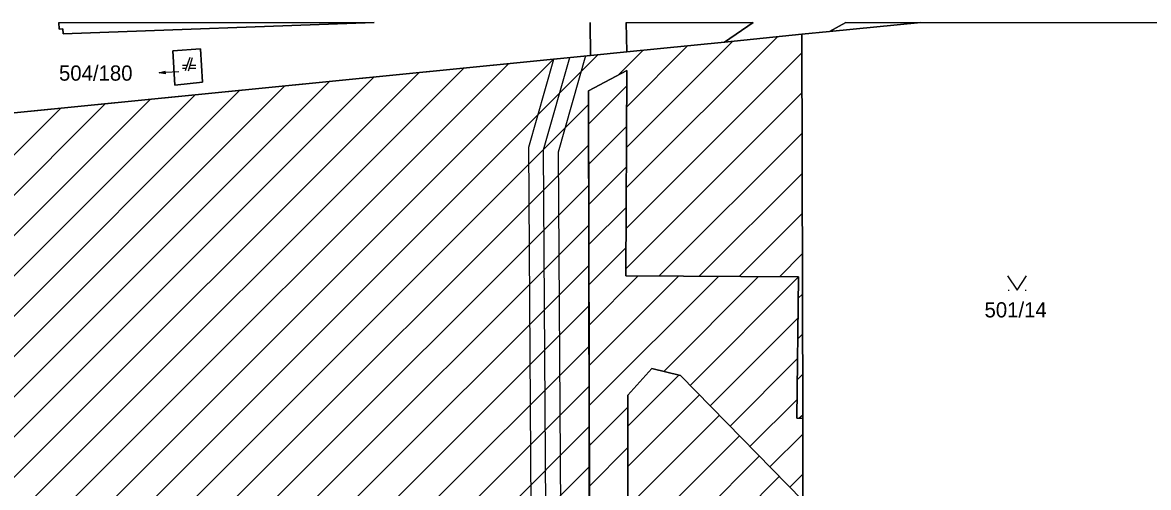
# Model space of a CAD drawing. Extents: x -264309 to -263505, y -1242443 to -1241763.
# Drawn here: x -264073.7 to -263955.2, y -1242005.9 to -1241957 of the extents above; entities that cross this region are included whole.
import ezdxf

# ---------------------------------------------------------------- set-up
doc = ezdxf.new("R2010")
doc.units = 0
for name, color, linetype in [('KN_2019_08_16', 7, 'Continuous'), ('KN_2019_08_16_KLADPAR', 7, 'Continuous'), ('SRAFY_PARCELY', 7, 'Continuous')]:
    doc.layers.add(name, color=color, linetype=linetype)

msp = doc.modelspace()

# ---------------------------------------------------------------- linework, layer by layer
at = {"layer": 'KN_2019_08_16'}
msp.add_lwpolyline([(-264014.44, -1241960.47), (-264017.32, -1241970.61), (-264016.97, -1242024.38), (-264017.48, -1242038.84), (-264017.6, -1242045.19), (-264017.74, -1242052.08), (-264018.07, -1242069.28), (-264018.14, -1242072.77), (-264019.68, -1242072.72), (-264021.23, -1242072.66), (-264021.16, -1242069.28), (-264020.83, -1242052.09), (-264020.73, -1242046.57), (-264020.58, -1242038.83), (-264020.07, -1242024.34), (-264020.4, -1241970.09), (-264017.76, -1241960.8), (-264016.1, -1241960.64)], close=True, dxfattribs=at)
msp.add_lwpolyline([(-264019.68, -1242072.72), (-264019.61, -1242069.28), (-264019.28, -1242052.09), (-264019.16, -1242045.88), (-264019.03, -1242038.83), (-264018.52, -1242024.36), (-264018.86, -1241970.35), (-264016.1, -1241960.64)], dxfattribs=at)
at = {"layer": 'KN_2019_08_16_KLADPAR'}
for p, q in [((-264069.82, -1241957.65), (-264069.84, -1241956.96)), ((-264069.84, -1241956.96), (-264036.67, -1241956.96)), ((-264036.67, -1241956.96), (-264069.4, -1241958.16)), ((-264010.18, -1241956.96), (-263996.79, -1241956.96)), ((-264010.08, -1241960.03), (-264010.18, -1241956.96)), ((-263996.79, -1241956.96), (-263999.84, -1241959.01)), ((-263988.77, -1241957.91), (-263979.18, -1241956.96)), ((-263979.18, -1241956.96), (-263988.77, -1241957.91)), ((-263988.77, -1241957.91), (-263987.05, -1241956.96)), ((-263987.05, -1241956.96), (-263979.18, -1241956.96)), ((-263979.18, -1241956.96), (-263944.96, -1241956.96)), ((-264069.41, -1241957.63), (-264069.82, -1241957.65)), ((-264069.4, -1241958.16), (-264069.41, -1241957.63)), ((-263999.84, -1241959.01), (-263991.69, -1241958.2)), ((-263991.69, -1241958.2), (-263988.77, -1241957.91)), ((-263991.69, -1241958.2), (-263991.6, -1241998.65)), ((-263991.6, -1241998.65), (-263991.69, -1241958.2)), ((-264010.08, -1241960.03), (-263999.84, -1241959.01)), ((-263999.84, -1241959.01), (-264010.08, -1241960.03)), ((-264080.59, -1241967.06), (-264013.93, -1241960.42)), ((-264056.08, -1241960.64), (-264056.57, -1241962.04)), ((-264056.22, -1241962.04), (-264055.8, -1241960.64)), ((-264013.93, -1241960.42), (-264010.08, -1241960.03)), ((-264056.37, -1241961.48), (-264056.85, -1241961.48)), ((-264056.85, -1241961.76), (-264056.47, -1241961.76)), ((-264056.14, -1241961.76), (-264055.45, -1241961.76)), ((-264055.45, -1241961.48), (-264056.05, -1241961.48)), ((-264010.09, -1241962), (-264014.12, -1241964.15)), ((-264010.2, -1241983.62), (-264010.09, -1241962)), ((-264058.6, -1241962.35), (-264059.31, -1241962.24)), ((-264014.12, -1241964.15), (-264013.98, -1242038.21)), ((-263992.03, -1241983.73), (-264010.2, -1241983.62)), ((-263992.22, -1241998.61), (-263992.03, -1241983.73)), ((-263969.99, -1241985.12), (-263969.89, -1241985.12)), ((-263968.19, -1241985.12), (-263968.09, -1241985.12)), ((-263991.6, -1241998.65), (-263992.22, -1241998.61)), ((-263991.58, -1242007.28), (-263991.6, -1241998.65))]:
    msp.add_line(p, q, dxfattribs=at)
for points in [[(-264013.95, -1241956.96), (-264013.93, -1241960.42), (-264080.59, -1241967.06)], [(-264069.84, -1241956.96), (-264069.82, -1241957.65), (-264069.41, -1241957.63), (-264069.4, -1241958.16), (-264036.67, -1241956.96)], [(-264010.18, -1241956.96), (-264010.08, -1241960.03), (-264013.93, -1241960.42), (-264013.95, -1241956.96)], [(-263987.05, -1241956.96), (-263988.77, -1241957.91), (-263991.69, -1241958.2), (-263999.84, -1241959.01), (-263996.79, -1241956.96)], [(-264057.21, -1241962.14), (-264059.31, -1241962.24), (-264058.61, -1241962.07)], [(-264013.98, -1242038.21), (-264014.12, -1241964.15), (-264010.09, -1241962), (-264010.2, -1241983.62), (-263992.03, -1241983.73), (-263992.22, -1241998.61), (-263991.6, -1241998.65), (-263991.58, -1242007.28), (-264004.45, -1241994.11), (-264007.47, -1241993.39), (-264009.98, -1241996.19), (-264009.97, -1242022.53)], [(-263970.04, -1241983.62), (-263969.04, -1241985.12), (-263968.04, -1241983.62)]]:
    msp.add_lwpolyline(points, dxfattribs=at)
for points in [[(-264057.65, -1241963.54), (-264054.72, -1241963.25), (-264054.95, -1241959.73), (-264057.87, -1241959.95)], [(-264057.87, -1241959.95), (-264054.95, -1241959.73), (-264054.72, -1241963.25), (-264057.65, -1241963.54)], [(-263991.54, -1242026.1), (-264000.91, -1242025.57), (-264009.05, -1242025.11), (-264009.97, -1242022.53), (-264009.98, -1241996.19), (-264007.47, -1241993.39), (-264004.45, -1241994.11), (-263991.58, -1242007.28)]]:
    msp.add_lwpolyline(points, close=True, dxfattribs=at)
at = {"layer": 'SRAFY_PARCELY'}
for p, q in [((-264010.15, -1241974.36), (-263994.24, -1241958.45)), ((-264010.13, -1241970.1), (-263998.95, -1241958.92)), ((-264010.11, -1241965.83), (-264003.67, -1241959.39)), ((-264102.68, -1242045.68), (-264017.81, -1241960.81)), ((-264101.29, -1242048.53), (-264013.1, -1241960.34)), ((-264011.01, -1241962.49), (-264008.38, -1241959.86)), ((-264010.17, -1241978.63), (-263991.69, -1241960.14)), ((-264105.47, -1242039.98), (-264027.23, -1241961.75)), ((-264104.08, -1242042.83), (-264022.52, -1241961.28)), ((-264109.63, -1242031.42), (-264041.37, -1241963.15)), ((-264108.26, -1242034.28), (-264036.66, -1241962.68)), ((-264106.86, -1242037.13), (-264031.95, -1241962.21)), ((-264113.66, -1242022.72), (-264055.51, -1241964.56)), ((-264112.32, -1242025.62), (-264050.79, -1241964.09)), ((-264110.98, -1242028.52), (-264046.08, -1241963.62)), ((-264014.11, -1241967.64), (-264010.1, -1241963.62)), ((-264010.2, -1241982.89), (-263991.68, -1241964.37)), ((-264116.35, -1242016.92), (-264064.93, -1241965.5)), ((-264115, -1242019.82), (-264060.22, -1241965.03)), ((-264099.9, -1242051.38), (-264014.12, -1241965.6)), ((-264117.69, -1242014.02), (-264069.64, -1241965.97)), ((-264014.11, -1241971.87), (-264010.12, -1241967.89)), ((-264006.7, -1241983.64), (-263991.67, -1241968.61)), ((-264098.59, -1242054.31), (-264014.11, -1241969.83)), ((-264014.1, -1241976.11), (-264010.14, -1241972.15)), ((-264002.49, -1241983.67), (-263991.66, -1241972.84)), ((-264097.28, -1242057.24), (-264014.1, -1241974.07)), ((-264014.09, -1241980.34), (-264010.16, -1241976.42)), ((-263998.27, -1241983.69), (-263991.65, -1241977.07)), ((-264095.96, -1242060.17), (-264014.09, -1241978.3)), ((-264014.08, -1241984.58), (-264010.19, -1241980.68)), ((-263994.05, -1241983.72), (-263991.64, -1241981.31)), ((-264094.65, -1242063.1), (-264014.09, -1241982.54)), ((-264014.07, -1241988.81), (-264008.89, -1241983.63)), ((-264014.07, -1241993.05), (-264004.67, -1241983.65)), ((-264014.06, -1241997.28), (-264000.45, -1241983.68)), ((-264006.22, -1241993.69), (-263996.24, -1241983.7)), ((-264003.44, -1241995.15), (-263992.03, -1241983.74)), ((-263992.06, -1241985.97), (-263991.63, -1241985.54)), ((-264093.34, -1242066.03), (-264014.08, -1241986.77)), ((-264001.34, -1241997.29), (-263992.09, -1241988.04)), ((-263992.11, -1241990.27), (-263991.62, -1241989.77)), ((-264092.02, -1242068.96), (-264014.07, -1241991.01)), ((-263999.24, -1241999.44), (-263992.14, -1241992.33)), ((-264009.98, -1241999.45), (-264004.61, -1241994.07)), ((-263992.17, -1241994.56), (-263991.61, -1241994)), ((-264069.58, -1242050.76), (-264014.06, -1241995.24)), ((-264009.98, -1242003.69), (-264002.45, -1241996.16)), ((-264014.05, -1242001.52), (-264009.98, -1241997.45)), ((-263997.15, -1242001.58), (-263992.19, -1241996.63)), ((-264009.98, -1242007.93), (-264000.35, -1241998.3)), ((-263991.99, -1241998.62), (-263991.6, -1241998.24)), ((-264062.86, -1242048.29), (-264014.05, -1241999.48)), ((-264009.97, -1242012.17), (-263998.25, -1242000.45)), ((-263995.05, -1242003.73), (-263991.6, -1242000.28)), ((-264014.04, -1242005.75), (-264009.98, -1242001.69)), ((-264009.97, -1242016.41), (-263996.16, -1242002.6)), ((-264058.6, -1242048.27), (-264014.05, -1242003.71)), ((-264009.97, -1242020.65), (-263994.06, -1242004.74)), ((-263992.95, -1242005.88), (-263991.59, -1242004.51))]:
    msp.add_line(p, q, dxfattribs=at)

# ---------------------------------------------------------------- texts
at = {"layer": 'KN_2019_08_16_KLADPAR'}
for s, p in [('504/180', (-264069.83, -1241963.08)), ('501/14', (-263972.47, -1241988))]:
    msp.add_text(s, height=1.6, dxfattribs=at).set_placement(p)

doc.saveas('drawing.dxf')
